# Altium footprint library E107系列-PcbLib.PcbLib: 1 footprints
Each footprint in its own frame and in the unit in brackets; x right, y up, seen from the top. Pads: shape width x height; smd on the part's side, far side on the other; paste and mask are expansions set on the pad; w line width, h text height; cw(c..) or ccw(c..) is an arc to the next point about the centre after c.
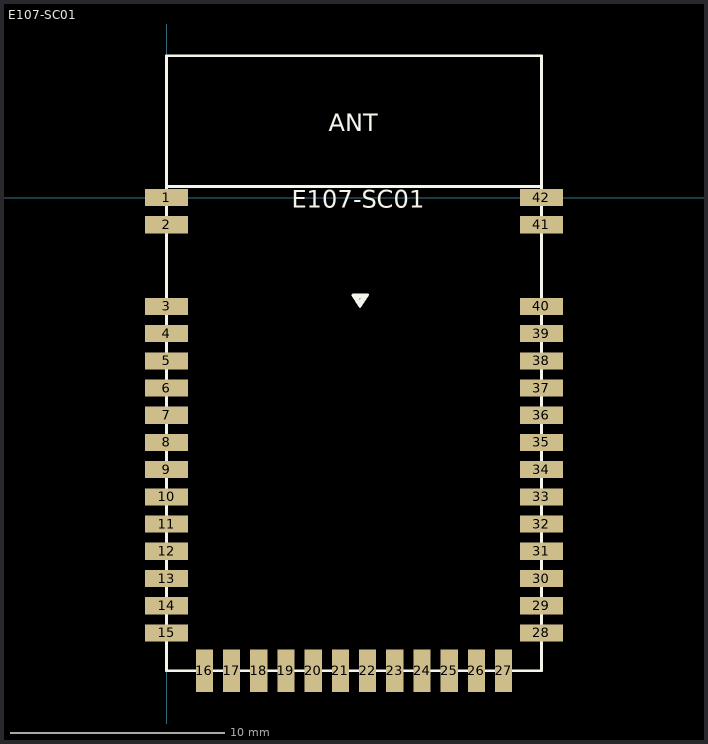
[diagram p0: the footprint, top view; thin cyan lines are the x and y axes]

## E107-SC01 [mm] "28.7mm*17.5mm*1.78mm-S"
pads (42):
  rect 2x0.8 smd: 1(0,0) 2(0,-1.27) 3(0,-5.08) 4(0,-6.35) 5(0,-7.62) 6(0,-8.89) 7(0,-10.16) 8(0,-11.43) 9(0,-12.7) 10(0,-13.97) 11(0,-15.24) 12(0,-16.51) 13(0,-17.78) 14(0,-19.05) 15(0,-20.32) 28(17.5,-20.32) 29(17.5,-19.05) 30(17.5,-17.78) 31(17.5,-16.51) 32(17.5,-15.24) 33(17.5,-13.97) 34(17.5,-12.7) 35(17.5,-11.43) 36(17.5,-10.16) 37(17.5,-8.89) 38(17.5,-7.62) 39(17.5,-6.35) 40(17.5,-5.08) 41(17.5,-1.27) 42(17.5,0)
  rect 0.8x2 smd: 16(1.765,-22.085) 17(3.035,-22.085) 18(4.305,-22.085) 19(5.575,-22.085) 20(6.845,-22.085) 21(8.115,-22.085) 22(9.385,-22.085) 23(10.655,-22.085) 24(11.925,-22.085) 25(13.195,-22.085) 26(14.465,-22.085) 27(15.735,-22.085)
Top Overlay:
  lines w0.1: 8.709,-4.532 9.409,-4.532 9.029,-5.102 8.689,-4.562 9.279,-4.592 9.049,-4.942 8.799,-4.622 9.159,-4.682 9.019,-4.812 8.939,-4.712 9.159,-4.622 9.049,-5.022
  lines w0.127: 0,0.519 17.5,0.519 ; 0,-22.085 17.5,-22.085 17.5,6.615 0,6.615 0,-22.085
  text "ANT" at 7.576,2.817 h1.4
  text "E107-SC01" at 5.842,-0.762 h1.4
